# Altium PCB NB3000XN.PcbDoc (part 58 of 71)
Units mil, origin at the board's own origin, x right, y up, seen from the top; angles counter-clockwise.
Board outline 9527.56 x 6929.77 mil, 6 copper layers (Top Layer, GND+SHIELD, MidLayer1, MidLayer2, P2 - 3V3+5V0, Bottom Layer), stack 62.375 mil thick; 832 components, 1027 nets, 4655 pads, 4981 vias.
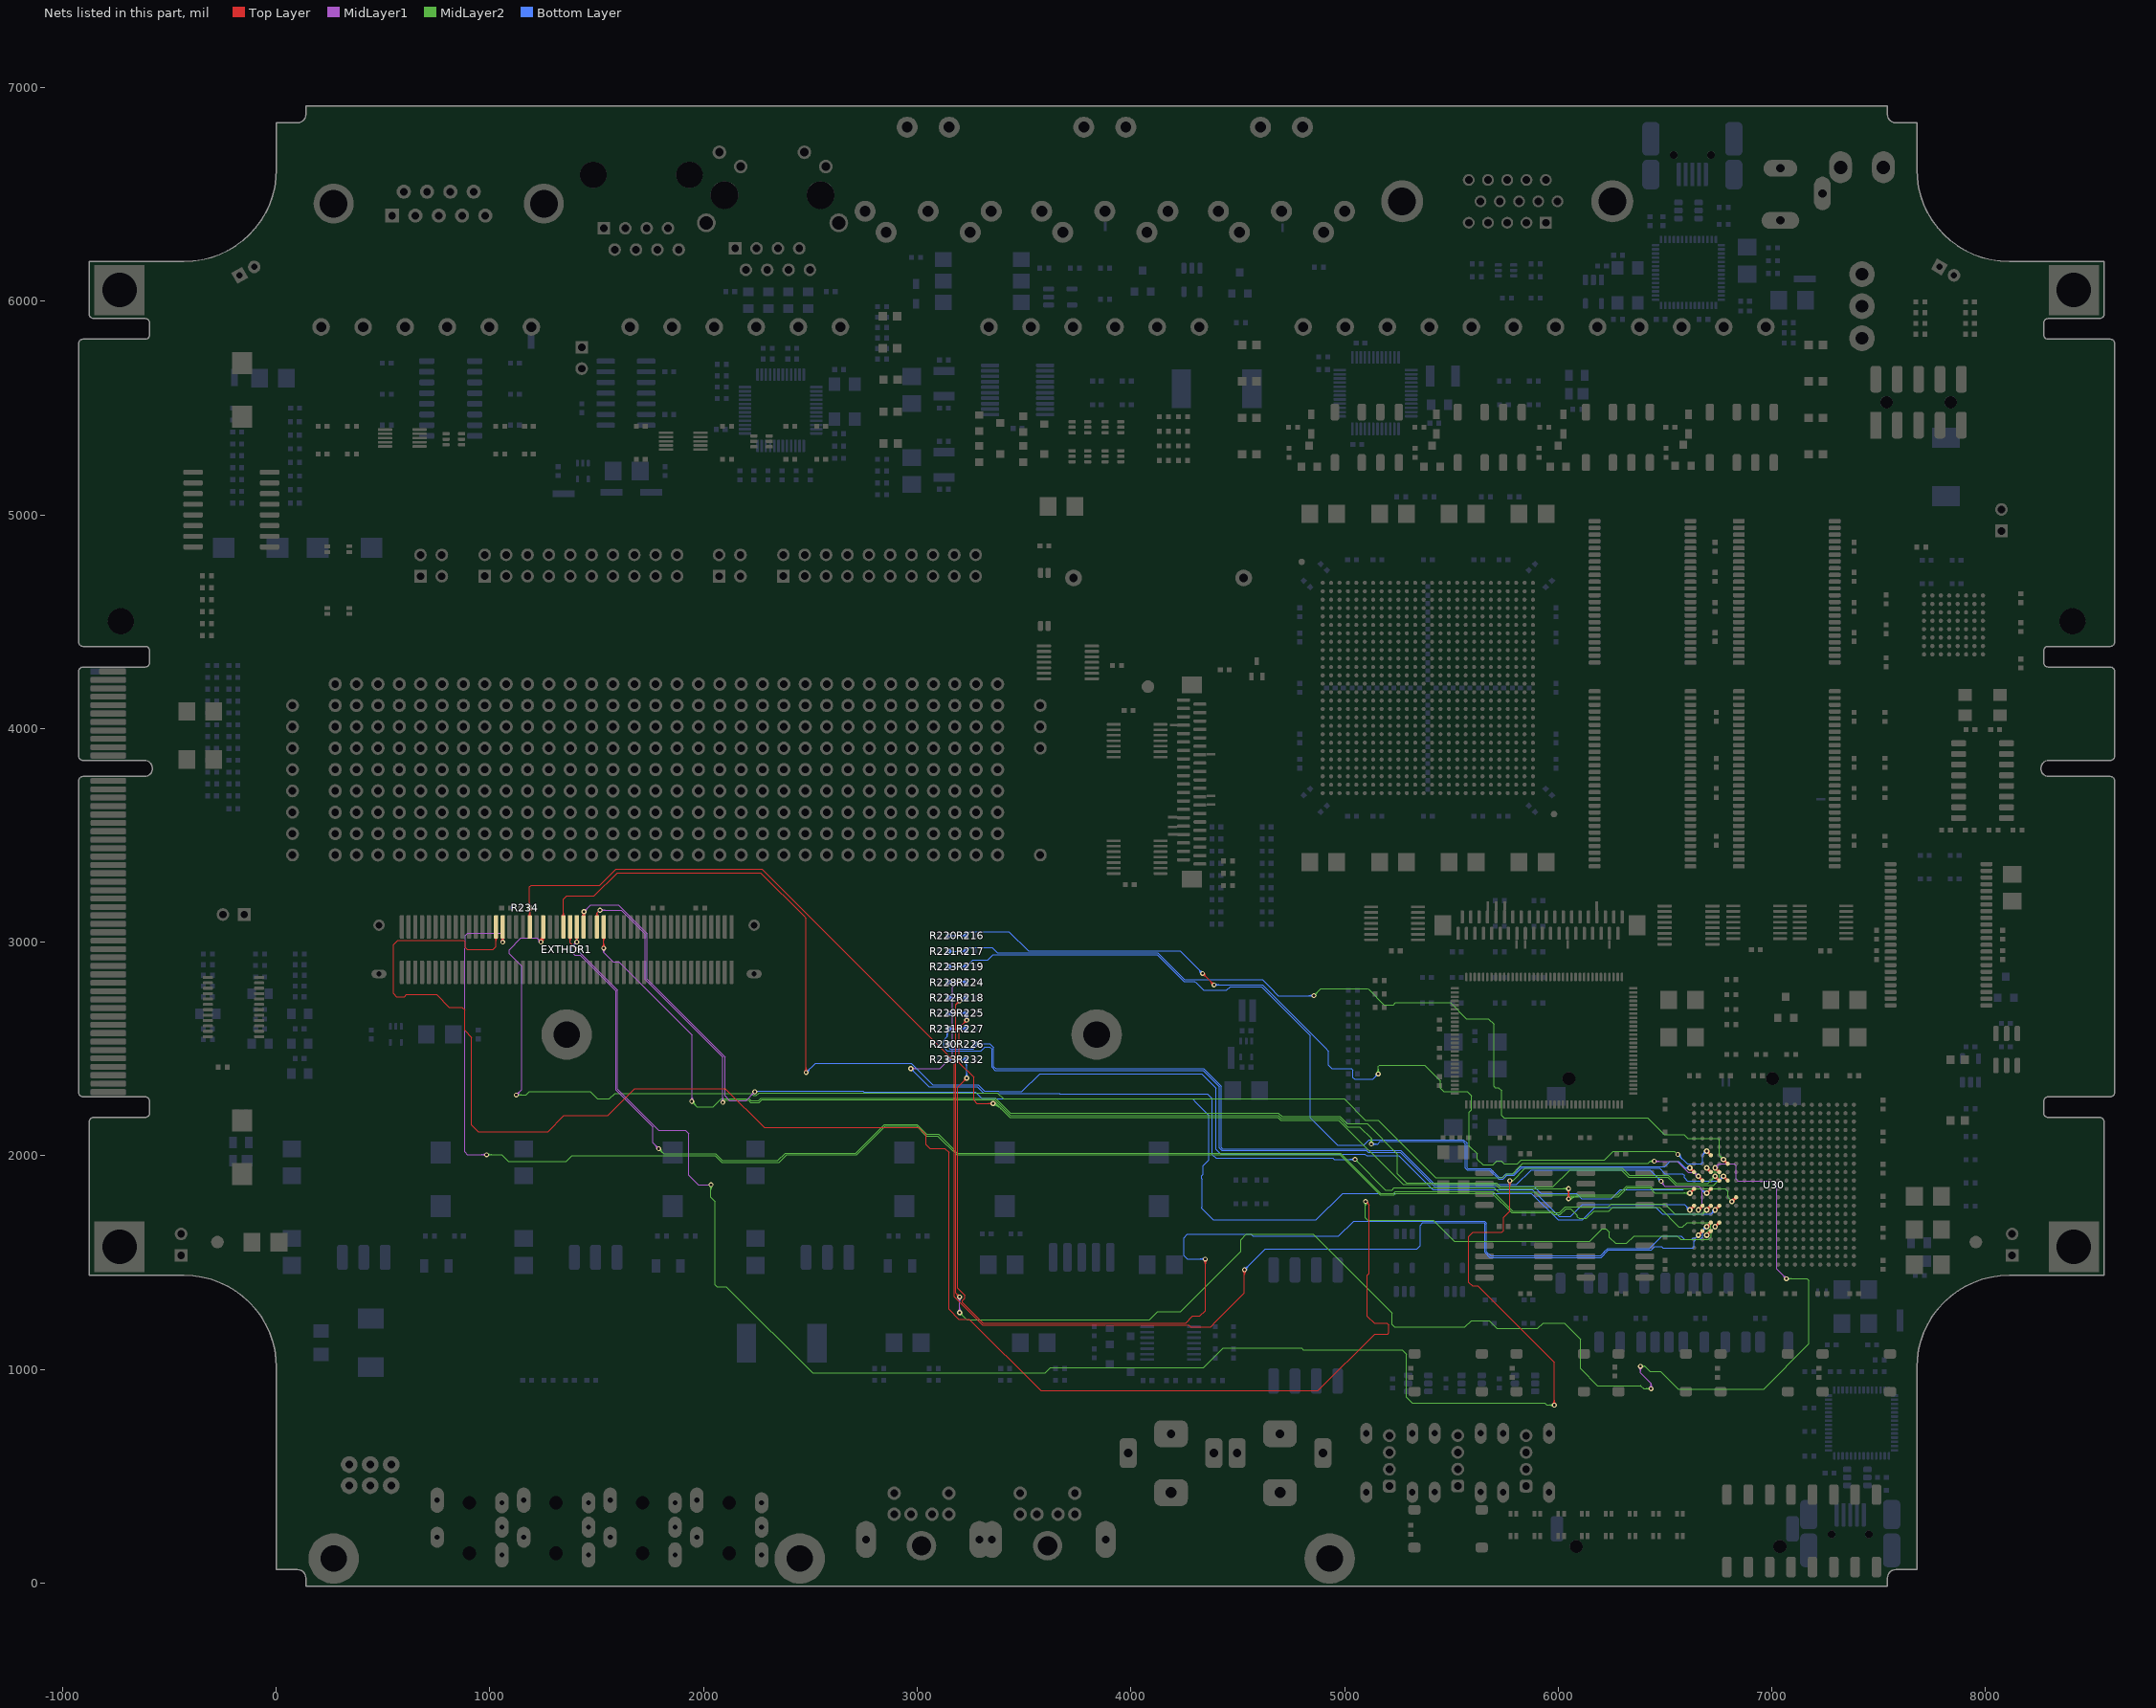
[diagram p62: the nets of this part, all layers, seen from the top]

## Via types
v1: diameter 23, hole 11.81, Top Layer to Bottom Layer, 3672 vias
v2: diameter 26, hole 11.81, Top Layer to Bottom Layer, 461 vias
v3: diameter 19, hole 11.81, Top Layer to Bottom Layer, tented both sides, 396 vias
v4: diameter 23.62, hole 11.81, Top Layer to Bottom Layer, 288 vias
v5: diameter 20, hole 11.81, Top Layer to Bottom Layer, 91 vias
v6: diameter 23, hole 11.81, Top Layer to Bottom Layer, tented both sides, 50 vias
v7: diameter 31, hole 11.81, Top Layer to Bottom Layer, 15 vias
v8: diameter 27.56, hole 11.81, Top Layer to Bottom Layer, tented both sides, 4 vias
v9: diameter 29, hole 11.81, Top Layer to Bottom Layer, 3 vias
v10: diameter 21, hole 11.81, Top Layer to Bottom Layer, 1 vias

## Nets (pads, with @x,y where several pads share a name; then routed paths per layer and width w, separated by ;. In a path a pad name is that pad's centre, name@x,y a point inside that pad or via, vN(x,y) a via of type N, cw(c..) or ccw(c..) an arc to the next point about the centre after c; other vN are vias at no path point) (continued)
PB_SPI.SCLK: EXTHDR1.57 U30.W10 | length 7349.8
  Top Layer w4: v1@1232.79,3007.44 ccw(c1192.61,3047.62) EXTHDR1.57@1249.43,3047.62 ; v1@1235.62,3004.61 ccw(c1202.27,3037.97) EXTHDR1.57@1249.43,3037.97 ; v1@1238.45,3001.79 ccw(c1211.92,3028.31) EXTHDR1.57@1249.43,3028.31 ; v1(1239.51,3000.72) 1240.19,3000.04 1249.43,3009.28 ; v1@1241.27,2998.96 ccw(c1221.58,3018.65) EXTHDR1.57@1249.43,3018.65 ; v1@1244.1,2996.13 ccw(c1231.24,3008.99) 1249.43,3008.99 ; EXTHDR1.57@1244.21,3020.67 cw(c1234.41,3009.28) 1249.43,3009.28 ; EXTHDR1.57@1249.43,3071.85 1249.43,3009.28 ; EXTHDR1.57@1254.65,3020.67 ccw(c1264.46,3009.28) 1249.43,3009.28
  Top Layer w8: v2@6655.67,1895.37 cw(c6655.67,1873.64) 6671.03,1889.01 cw(c6686.4,1904.37) v2@6664.67,1904.37 ; v2(6655.67,1904.37) U30.W10@6675.35,1884.68 ; U30.W10@6669.51,1884.68 ccw(c6655.41,1884.68) 6665.38,1894.66 ccw(c6675.35,1904.63) U30.W10@6675.35,1890.53
  MidLayer1 w4: v1(1123.52,2285.04) 1148.86,2310.37 1148.86,2888 1090,2946.86 1090,2965 1145,3020 1220.23,3020 v1(1239.51,3000.72) ; v1@1123.52,2290.54 ccw(c1123.52,2303.82) 1132.91,2294.43 ccw(c1142.3,2285.04) v1@1129.02,2285.04 ; v1@1123.52,2294.54 ccw(c1123.52,2317.48) 1139.74,2301.26 ccw(c1155.96,2285.04) v1@1133.02,2285.04 ; v1@1230.01,3000.72 ccw(c1207.07,3000.72) 1223.29,3016.94 ccw(c1239.51,3033.16) v1@1239.51,3010.22 ; v1@1234.01,3000.72 ccw(c1220.73,3000.72) 1230.12,3010.11 ccw(c1239.51,3019.5) v1@1239.51,3006.22 ; v1(6449.52,1975.04) 6556.86,1975.04 6608.19,1923.71 6636.33,1923.71 v2(6655.67,1904.37) ; v1@6453.41,1971.15 cw(c6462.8,1961.76) 6462.8,1975.04 cw(c6462.8,1988.32) v1@6453.41,1978.93 ; v1@6456.24,1968.32 cw(c6472.46,1952.11) 6472.46,1975.04 cw(c6472.46,1997.98) v1@6456.24,1981.76 ; v2@6644.67,1904.37 ccw(c6618.11,1904.37) 6636.89,1923.15 ccw(c6655.67,1941.93) v2@6655.67,1915.37 ; v2@6648.67,1904.37 ccw(c6631.77,1904.37) 6643.72,1916.32 ccw(c6655.67,1928.27) v2@6655.67,1911.37
  MidLayer2 w4: v1(1123.52,2285.04) 1170.04,2285.04 1185.37,2300.37 1469.63,2300.37 1503.29,2266.71 1560,2266.71 1585.29,2292 2223.25,2292 2232.75,2282.5 2247.25,2282.5 2259.25,2294.5 3375.5,2294.5 3403.3,2266.71 4998.52,2266.71 5098.52,2166.71 5156.86,2166.71 5425.7,1897.87 5740.64,1897.87 5759.65,1916.87 5786.05,1916.87 5815.71,1946.54 5834.88,1965.71 6420.71,1965.71 6430.04,1975.04 ; v1@1127.41,2281.15 cw(c1136.8,2271.76) 1136.8,2285.04 cw(c1136.8,2298.32) v1@1127.41,2288.93 ; v1@1130.24,2278.32 cw(c1146.46,2262.11) 1146.46,2285.04 cw(c1146.46,2307.98) v1@1130.24,2291.76 ; v1@6442.04,1969.19 ccw(c6430.04,1959.81) 6430.04,1975.04 ; v1@6442.04,1980.89 cw(c6430.04,1990.27) 6430.04,1975.04 ; v1(6449.52,1975.04) 6430.04,1975.04
PBCTRL.1W.ID: EXTHDR1.61 R234.1 U30.V15 | length 8232
  Top Layer w4: R234.1@1179.59,3152.92 cw(c1163.06,3136.38) 1186.44,3136.38 ; R234.1@1179.59,3167.08 ccw(c1163.68,3182.99) 1186.18,3182.99 ccw(c1208.68,3182.99) R234.1@1192.77,3167.08 ; EXTHDR1.61@1180.78,3122.62 ccw(c1167.12,3136.28) 1186.44,3136.28 ccw(c1205.75,3136.28) EXTHDR1.61@1192.1,3122.62 ; R234.1@1182.42,3155.75 cw(c1172.71,3146.04) 1186.44,3146.04 ; R234.1@1182.42,3164.25 ccw(c1173.34,3173.33) 1186.18,3173.33 ccw(c1199.02,3173.33) R234.1@1189.94,3164.25 ; EXTHDR1.61@1186.44,3071.85 1186.44,3159.74 R234.1@1186.18,3160 1186.18,3258.71 1194.18,3266.71 1515.19,3266.71 1590.19,3341.71 2273.52,3341.71 3112.7,2502.53 3173.19,2442.04 3173.19,1340.35 3305.17,1208.37 4271.63,1208.37 4280,1200 4373.48,1200 4400.9,1227.42 4531.86,1358.37 v1(4531.86,1466.71) ; 1186.44,3137.64 cw(c1208.05,3137.64) R234.1@1192.77,3152.92 ; 1186.44,3147.29 cw(c1198.4,3147.29) R234.1@1189.94,3155.75 ; v1@4525.14,1459.99 cw(c4508.92,1443.77) 4531.86,1443.77 cw(c4554.79,1443.77) v1@4538.57,1459.99 ; v1@4527.97,1462.82 cw(c4518.58,1453.43) 4531.86,1453.43 cw(c4545.14,1453.43) v1@4535.75,1462.82
  Top Layer w8: v2(6695.04,1668.15) U30.V15@6714.72,1687.83 ; v2@6695.04,1677.15 ccw(c6695.04,1698.88) 6710.4,1683.51 ccw(c6725.77,1668.15) v2@6704.04,1668.15 ; U30.V15@6708.88,1687.83 cw(c6694.78,1687.83) 6704.75,1677.86 cw(c6714.72,1667.89) U30.V15@6714.72,1681.99
  Bottom Layer w4: v1(4531.86,1466.71) 4630.15,1565 5340,1565 5355,1580 5355,1675 5367,1687 5651.69,1687 5657,1681.69 5657,1548.04 5680,1525.04 6202.19,1525.04 6235.86,1558.71 6436.52,1558.71 6452.86,1575.04 6484.52,1575.04 6490.19,1569.37 6631.52,1569.37 6635.52,1573.37 6635.52,1600.04 6644.19,1608.71 6662.86,1608.71 6675.52,1621.37 6675.52,1648.63 v2(6695.04,1668.15) ; v1@4531.86,1472.21 ccw(c4531.86,1485.49) 4541.25,1476.1 ccw(c4550.64,1466.71) v1@4537.36,1466.71 ; v1@4531.86,1476.21 ccw(c4531.86,1499.14) 4548.07,1482.93 ccw(c4564.29,1466.71) v1@4541.36,1466.71 ; 6683.09,1656.2 ccw(c6671.14,1668.15) v2@6688.04,1668.15 ; 6683.09,1656.2 cw(c6695.04,1644.25) v2@6695.04,1661.15 ; v2@6684.04,1668.15 cw(c6657.48,1668.15) 6676.26,1649.37 cw(c6695.04,1630.6) v2@6695.04,1657.15
PBCTRL.1W.PIO1: EXTHDR1.69 U30.V16 | length 7898.4
  Top Layer w4: v1@1053.74,3007.17 ccw(c1037.52,3023.39) 1060.46,3023.39 ccw(c1083.39,3023.39) v1@1067.17,3007.17 ; v1@1056.57,3004.34 ccw(c1047.18,3013.73) 1060.46,3013.73 ccw(c1073.73,3013.73) v1@1064.34,3004.34 ; v1(1060.46,3000.46) EXTHDR1.69@1060.46,3071.85
  Top Layer w8: v2(6695.04,1628.78) U30.V16@6714.72,1648.46 ; v2@6695.04,1637.78 ccw(c6695.04,1659.51) 6710.4,1644.14 ccw(c6725.77,1628.78) v2@6704.04,1628.78 ; U30.V16@6708.88,1648.46 cw(c6694.78,1648.46) 6704.75,1638.49 cw(c6714.72,1628.52) U30.V16@6714.72,1642.62
  MidLayer1 w4: v1@978.28,1998.28 ccw(c962.06,1982.06) 962.06,2005 ccw(c962.06,2027.93) v1@978.28,2011.72 ; v1@981.11,2001.11 ccw(c971.72,1991.72) 971.72,2005 ccw(c971.72,2018.28) v1@981.11,2008.89 ; v1(985,2005) 895,2005 881.86,2018.14 881.86,2970.71 886.19,2975.04 886.19,3031.19 896.71,3041.71 1053.29,3041.71 1060.46,3034.54 v1(1060.46,3000.46) ; v1@1053.74,3007.17 ccw(c1037.52,3023.39) 1060.46,3023.39 ccw(c1083.39,3023.39) v1@1067.17,3007.17 ; v1@1056.57,3004.34 ccw(c1047.18,3013.73) 1060.46,3013.73 ccw(c1073.73,3013.73) v1@1064.34,3004.34
  MidLayer2 w4: v1(985,2005) 1055,2005 1086.69,1973.31 1358.27,1973.31 1385,2000.04 2055,2000.04 2065.04,1990 2085.04,1970 2354.96,1970 2389.77,2004.81 2716.63,2004.81 2850.82,2139 2995.87,2139 3041.37,2093.5 3095.73,2093.5 3184.42,2004.81 4978.09,2004.81 5166.19,1816.71 5232.47,1816.71 5240.8,1825.04 5690.19,1825.04 5781.86,1733.37 5970.54,1733.37 5978.92,1725 5995,1725 6009.52,1725.04 6037.19,1752.71 6057.86,1752.71 6090.19,1720.37 6090.19,1715.04 6098.52,1706.71 6131.86,1706.71 6166.86,1741.71 6237.82,1741.71 6254.49,1758.37 6473.52,1758.37 6565.19,1666.71 6581.86,1666.71 6603.52,1688.37 6680,1688.37 6681.23,1687.15 6702.91,1687.15 6714.04,1676.02 6714.04,1660.28 6695.04,1641.28 v2(6695.04,1628.78) ; v1@988.89,2001.11 cw(c998.28,1991.72) 998.28,2005 cw(c998.28,2018.28) v1@988.89,2008.89 ; v1@991.72,1998.28 cw(c1007.93,1982.06) 1007.93,2005 cw(c1007.93,2027.93) v1@991.72,2011.72
PBCTRL.1W.PIO2: EXTHDR1.71 U30.U15 | length 10109.7
  Top Layer w4: EXTHDR1.71@1023.3,3021.07 cw(c1009.65,3007.42) 1028.96,3007.42 cw(c1048.27,3007.42) EXTHDR1.71@1034.62,3021.07 ; EXTHDR1.71@1031.86,3075.04 1028.96,3075.04 EXTHDR1.71@1028.96,3071.85 1028.96,2980.48 1015.19,2966.71 894.52,2966.71 886.19,2975.04 886.19,3000.04 877.86,3008.37 568.37,3008.37 548.52,2988.52 548.52,2760 563.52,2745 600,2745 610,2755 750,2755 810,2695 870,2695 881.86,2683.14 881.86,2588.14 915,2555 915,2143.9 944.9,2114 1271.63,2114 1346.63,2189 1552.94,2189 1678.94,2315 2101.06,2315 2284.06,2132 3006.69,2132 3042,2096.69 3042,2053 3060,2035 3130,2035 3148.86,2016.14 3148.86,1281.14 3195,1235 3243.92,1235 3578.54,900.37 4875.37,900.37 5141.71,1166.71 5201.71,1166.71 5206.69,1171.69 5206.69,1208.31 5198.29,1216.71 5139.19,1216.71 5106.86,1249.04 5106.86,1441.71 5115.19,1450.04 5115.19,1770.04 v1(5098.52,1786.71) ; v1@5098.52,1777.21 cw(c5098.52,1754.27) 5114.74,1770.49 cw(c5130.96,1786.71) v1@5108.02,1786.71 ; v1@5098.52,1781.21 cw(c5098.52,1767.93) 5107.91,1777.32 cw(c5117.3,1786.71) v1@5104.02,1786.71
  Top Layer w8: v2(6734.41,1668.15) U30.U15@6754.09,1687.83 ; v2@6734.41,1677.15 ccw(c6734.41,1698.88) 6749.77,1683.51 ccw(c6765.14,1668.15) v2@6743.41,1668.15 ; U30.U15@6748.25,1687.83 cw(c6734.15,1687.83) 6744.12,1677.86 cw(c6754.09,1667.89) U30.U15@6754.09,1681.99
  MidLayer2 w4: v1@5092.62,1779.27 cw(c5082.92,1767.04) 5098.52,1767.04 cw(c5114.13,1767.04) v1@5104.43,1779.27 ; v1(5098.52,1786.71) 5098.52,1709.48 5109.29,1698.71 5414.76,1698.71 5513.43,1600.04 6147.52,1600.04 6205.86,1658.37 6223.52,1658.37 6240.19,1641.71 6240.19,1619.04 6268.52,1590.71 6320.67,1590.71 6355,1625.04 6558.19,1625.04 6573.52,1609.71 6655,1609.71 6655.07,1609.78 6702.91,1609.78 6715.41,1622.28 6715.41,1649.15 v2@6732.97,1666.71 ; v2@6731.86,1666.71 v2@6732.97,1666.71 ; v2@6732.97,1666.71 6734.4,1666.71 v2(6734.41,1668.15) v2@6732.97,1666.71
PBCTRL.CLK.CLK0: EXTHDR1.51 U30.Y13 | length 7160.4
  Top Layer w4: EXTHDR1.51@1338.26,3122.62 ccw(c1324.61,3136.28) 1343.92,3136.28 ccw(c1363.23,3136.28) EXTHDR1.51@1349.58,3122.62 ; EXTHDR1.51@1343.92,3071.85 1343.92,3200.79 1360.17,3217.04 1488.15,3217.04 1596.15,3325.04 2267.56,3325.04 2467.3,3125.3 2480,3112.6 v1(2480,2390) ; v1@2473.28,2396.72 ccw(c2457.06,2412.93) 2480,2412.93 ccw(c2502.93,2412.93) v1@2486.72,2396.72 ; v1@2476.11,2393.89 ccw(c2466.72,2403.28) 2480,2403.28 ccw(c2493.28,2403.28) v1@2483.89,2393.89
  Top Layer w8: v2(6616.3,1746.89) U30.Y13@6635.98,1766.57 ; v2@6616.3,1755.89 ccw(c6616.3,1777.62) 6631.66,1762.25 ccw(c6647.03,1746.89) v2@6625.3,1746.89 ; U30.Y13@6630.14,1766.57 cw(c6616.04,1766.57) 6626.01,1756.6 cw(c6635.98,1746.63) U30.Y13@6635.98,1760.73
  Bottom Layer w4: v1(2480,2390) 2523.37,2433.37 2971.67,2433.37 3073.54,2331.5 3285.34,2331.5 3314.34,2302.5 3378.82,2302.5 3381.28,2300.04 3490.19,2300.04 3573.52,2383.37 4331.86,2383.37 4398.52,2316.71 4398.52,2050 ; v1@2480,2395.5 ccw(c2480,2408.78) 2489.39,2399.39 ccw(c2498.78,2390) v1@2485.5,2390 ; v1@2480,2399.5 ccw(c2480,2422.43) 2496.22,2406.22 ccw(c2512.43,2390) v1@2489.5,2390 ; 4398.52,2035 4398.52,2050 ; v2@6605.3,1746.89 ccw(c6578.74,1746.89) 6597.52,1765.67 ccw(c6616.3,1784.45) v2@6616.3,1757.89 ; v2@6609.3,1746.89 ccw(c6592.4,1746.89) 6604.35,1758.84 ccw(c6616.3,1770.79) v2@6616.3,1753.89 ; v2(6616.3,1746.89) 6590.76,1772.43 6114.24,1772.43 6058.52,1716.71 6004.86,1716.71 5879.86,1841.71 5412.21,1841.71 5253.21,2000.71 5103.94,2000.71 5096.27,2008.37 4420,2008.37 4398.52,2029.85 4398.52,2050
PBCTRL.CLK.CLK1: EXTHDR1.45 U30.U13 | length 7057.2
  Top Layer w4: EXTHDR1.45@1432.75,3122.62 ccw(c1419.09,3136.28) 1438.41,3136.28 ccw(c1457.72,3136.28) EXTHDR1.45@1444.07,3122.62 ; v1@1433.47,3136.32 cw(c1421.55,3124.41) EXTHDR1.45@1438.41,3124.41 ; EXTHDR1.45@1438.41,3071.85 v1@1438.41,3141.26 ; EXTHDR1.45@1438.41,3115.81 cw(c1467.42,3115.81) v1@1446.91,3136.32 ; EXTHDR1.45@1438.41,3125.46 cw(c1457.77,3125.46) v1@1444.08,3139.15
  Top Layer w8: v2(6734.41,1746.89) U30.U13@6754.09,1766.57 ; v2@6734.41,1755.89 ccw(c6734.41,1777.62) 6749.77,1762.25 ccw(c6765.14,1746.89) v2@6743.41,1746.89 ; U30.U13@6748.25,1766.57 cw(c6734.15,1766.57) 6744.12,1756.6 cw(c6754.09,1746.63) U30.U13@6754.09,1760.73
  MidLayer1 w4: v1(1440.19,3143.04) 1472.19,3175.04 1600.9,3175.04 1735,3040.94 1735,2827.86 1771.25,2791.61 2100,2462.86 2100,2280 2120.63,2259.37 2199.37,2259.37 v1(2240,2300) ; v1@1440.19,3148.54 ccw(c1440.19,3161.82) 1449.58,3152.43 ccw(c1458.97,3143.04) v1@1445.69,3143.04 ; v1@1440.19,3152.54 ccw(c1440.19,3175.48) 1456.41,3159.26 ccw(c1472.63,3143.04) v1@1449.69,3143.04 ; v1@2230.5,2300 cw(c2207.56,2300) 2223.78,2283.78 cw(c2240,2267.56) v1@2240,2290.5 ; v1@2234.5,2300 cw(c2221.22,2300) 2230.61,2290.61 cw(c2240,2281.22) v1@2240,2294.5
  Bottom Layer w4: v1(2240,2300) 2243,2303 2745.94,2303 2749.44,2299.5 3272.08,2299.5 3301.08,2270.5 3365.56,2270.5 3369.19,2266.87 4288.31,2266.87 4305.35,2249.84 4365.52,2189.66 4365.52,1980.81 4338,1953.29 4338,1914.27 4331.02,1907.29 4331.02,1892.79 4333,1890.82 4333,1761.69 4331.02,1759.71 4331.02,1754.23 4385.21,1700.04 4650,1700.04 4867.56,1700.04 4992.56,1825.04 5873.9,1825.04 5998.9,1700.04 6115.19,1700.04 6173.36,1758.21 6457.02,1758.21 6487.34,1727.89 6715.41,1727.89 v2(6734.41,1746.89) ; v2@6723.41,1746.89 cw(c6696.85,1746.89) 6715.63,1728.11 cw(c6734.41,1709.33) v2@6734.41,1735.89 ; v2@6727.41,1746.89 cw(c6710.51,1746.89) 6722.46,1734.94 cw(c6734.41,1722.99) v2@6734.41,1739.89
PBCTRL.CLK.CLK2: EXTHDR1.47 U30.V13 | length 6820.2
  Top Layer w4: EXTHDR1.47@1401.26,3021.07 cw(c1387.73,3007.55) v1@1406.86,3007.55 ; EXTHDR1.47@1405.05,3018.95 cw(c1404.49,3016.65) 1406.86,3016.65 ; EXTHDR1.47@1405.14,3018.93 cw(c1404.63,3016.71) 1406.91,3016.71 ; v1(1406.86,3001.04) 1406.86,3016.65 ; v1@1406.86,3007.28 cw(c1426.36,3007.28) EXTHDR1.47@1412.57,3021.07 ; EXTHDR1.47@1406.91,3071.85 1406.91,3016.71 ; 1406.86,3016.65 cw(c1409.19,3016.65) 1408.68,3018.93 ccw(c1409.19,3016.71) 1406.91,3016.71 ; 1406.86,3016.65 1406.91,3016.71
  Top Layer w8: v2(6695.04,1746.89) U30.V13@6714.72,1766.57 ; v2@6695.04,1755.89 ccw(c6695.04,1777.62) 6710.4,1762.25 ccw(c6725.77,1746.89) v2@6704.04,1746.89 ; U30.V13@6708.88,1766.57 cw(c6694.78,1766.57) 6704.75,1756.6 cw(c6714.72,1746.63) U30.V13@6714.72,1760.73
  MidLayer1 w4: v1@1397.36,3001.04 cw(c1374.42,3001.04) 1390.64,2984.82 cw(c1406.86,2968.61) v1@1406.86,2991.54 ; v1@1401.36,3001.04 cw(c1388.08,3001.04) 1397.47,2991.65 cw(c1406.86,2982.26) v1@1406.86,2995.54 ; v1(1406.86,3001.04) 1381.86,2976.04 1381.86,2955 1396.86,2940 1422.25,2940 1590.19,2772.06 1590.19,2308.5 1762.7,2135.99 1762.7,2060.87 v1(1790.19,2033.37) ; v1@1780.69,2033.37 ccw(c1757.76,2033.37) 1773.97,2049.59 ccw(c1790.19,2065.81) v1@1790.19,2042.87 ; v1@1784.69,2033.37 ccw(c1771.41,2033.37) 1780.8,2042.76 ccw(c1790.19,2052.15) v1@1790.19,2038.87
  MidLayer2 w4: v1@1790.19,2023.87 cw(c1790.19,2000.94) 1806.41,2017.16 cw(c1822.63,2033.37) v1@1799.69,2033.37 ; v1@1790.19,2027.87 cw(c1790.19,2014.6) 1799.58,2023.99 cw(c1808.97,2033.37) v1@1795.69,2033.37 ; v1(1790.19,2033.37) 1813.56,2010 2056.35,2010 2088.35,1978 2348,1978 2382.81,2012.81 2713.31,2012.81 2847.5,2147 2999.19,2147 3044.69,2101.5 3099.05,2101.5 3150.51,2050.04 3187.74,2012.81 4981.42,2012.81 5169.52,1824.71 5229.15,1824.71 5238.31,1833.87 5694.03,1833.87 5694.52,1833.37 5786.19,1741.71 5973.52,1741.71 5981.86,1733.37 6005.52,1733.37 6032.86,1760.71 6234.19,1760.71 6248.52,1775.04 6498.52,1775.04 6545.86,1727.71 6675.86,1727.71 v2(6695.04,1746.89) ; v2@6684.04,1746.89 cw(c6657.48,1746.89) 6676.26,1728.11 cw(c6695.04,1709.33) v2@6695.04,1735.89 ; v2@6688.04,1746.89 cw(c6671.14,1746.89) 6683.09,1734.94 cw(c6695.04,1722.99) v2@6695.04,1739.89
PBCTRL.CLK.EN: EXTHDR1.49 U30.U10 | length 9381.3
  Top Layer w4: EXTHDR1.49@1369.76,3021.07 cw(c1356.1,3007.42) 1375.42,3007.42 cw(c1394.73,3007.42) EXTHDR1.49@1381.07,3021.07 ; EXTHDR1.49@1375.42,3071.85 1375.42,2998.15 v1(1406.86,2966.71) ; v1@1397.36,2966.71 ccw(c1374.42,2966.71) 1390.64,2982.93 ccw(c1406.86,2999.14) v1@1406.86,2976.21 ; v1@1401.36,2966.71 ccw(c1388.08,2966.71) 1397.47,2976.1 ccw(c1406.86,2985.49) v1@1406.86,2972.21 ; v1@5766.81,1876.66 cw(c5750.59,1860.44) 5773.52,1860.44 cw(c5796.46,1860.44) v1@5780.24,1876.66 ; v1@5769.64,1879.49 cw(c5760.25,1870.1) 5773.52,1870.1 cw(c5786.8,1870.1) v1@5777.41,1879.49 ; v1(5773.52,1883.37) 5773.52,1741.71 5744.19,1712.37 5744.19,1650.04 5735.86,1641.71 5601.71,1641.71 5581.86,1621.86 5581.86,1408.37 5598.52,1391.71 5623.52,1391.71 5981.86,1033.37 v1(5981.86,833.37) ; v1@5975.14,840.09 ccw(c5958.92,856.31) 5981.86,856.31 ccw(c6004.79,856.31) v1@5988.57,840.09 ; v1@5977.97,837.26 ccw(c5968.58,846.65) 5981.86,846.65 ccw(c5995.14,846.65) v1@5985.75,837.26
  Top Layer w8: v2@6734.41,1895.37 cw(c6734.41,1873.64) 6749.77,1889.01 cw(c6765.14,1904.37) v2@6743.41,1904.37 ; v2(6734.41,1904.37) U30.U10@6754.09,1884.68 ; U30.U10@6748.25,1884.68 ccw(c6734.15,1884.68) 6744.12,1894.66 ccw(c6754.09,1904.63) U30.U10@6754.09,1890.53
  MidLayer1 w4: v1@1406.86,2957.21 cw(c1406.86,2934.27) 1423.07,2950.49 cw(c1439.29,2966.71) v1@1416.36,2966.71 ; v1@1406.86,2961.21 cw(c1406.86,2947.93) 1416.25,2957.32 cw(c1425.64,2966.71) v1@1412.36,2966.71 ; v1(1406.86,2966.71) 1598.19,2775.37 1598.19,2311.81 1790,2120 1915,2120 1930,2105 1930,1910.23 1975.23,1865 v1(2035,1865)
  MidLayer2 w4: v1@2028.28,1858.28 cw(c2012.06,1842.06) 2035,1842.06 cw(c2057.93,1842.06) v1@2041.72,1858.28 ; v1@2031.11,1861.11 cw(c2021.72,1851.72) 2035,1851.72 cw(c2048.28,1851.72) v1@2038.89,1861.11 ; v1(2035,1865) 2035,1805.23 2055,1785.23 2055,1397 2064,1388 2105.82,1388 2125.99,1367.83 2510.45,983.37 3598.52,983.37 3623.19,1008.04 4340,1008.04 4431.96,1100 4550,1100 4798.52,1100.04 4807.19,1091.37 5270.88,1091.37 5290.19,1072.06 5290.19,869.81 5317.13,842.87 5937.13,842.87 5946.63,833.37 v1(5981.86,833.37) ; v1(5773.52,1883.37) 5786.49,1883.37 5844.82,1941.71 6299.23,1941.71 6332.56,1908.37 6515.19,1908.37 6553.52,1870.04 6700.08,1870.04 v2(6734.41,1904.37) ; v1@5975.14,826.66 ccw(c5958.92,810.44) 5958.92,833.37 ccw(c5958.92,856.31) v1@5975.14,840.09 ; v1@5977.97,829.49 ccw(c5968.58,820.1) 5968.58,833.37 ccw(c5968.58,846.65) v1@5977.97,837.26 ; v2@6723.41,1904.37 cw(c6696.85,1904.37) 6715.63,1885.59 cw(c6734.41,1866.81) v2@6734.41,1893.37 ; v2@6727.41,1904.37 cw(c6710.51,1904.37) 6722.46,1892.42 cw(c6734.41,1880.47) v2@6734.41,1897.37
PBCTRL.JTAG.DETECT: R232.1 R233.1 U30.W16 | length 6012.9
  Top Layer w4: v1@3222.36,2363.71 cw(c3199.42,2363.71) 3215.64,2347.49 cw(c3231.86,2331.27) v1@3231.86,2354.21 ; v1@3226.36,2363.71 cw(c3213.08,2363.71) 3222.47,2354.32 cw(c3231.86,2344.93) v1@3231.86,2358.21 ; v1(3231.86,2363.71) 3189.19,2321.04 3189.19,1380.81 3222.5,1347.5 3222.5,1332.75 3212.25,1322.5 3212.25,1312.61 3308.15,1216.71 4256.67,1216.71 4290,1250.04 4323.52,1250.04 4348.52,1275.04 v1(4348.52,1516.71) ; v1@4341.81,1509.99 cw(c4325.59,1493.77) 4348.52,1493.77 cw(c4371.46,1493.77) v1@4355.24,1509.99 ; v1@4344.64,1512.82 cw(c4335.25,1503.43) 4348.52,1503.43 cw(c4361.8,1503.43) v1@4352.41,1512.82
  Top Layer w8: v2(6655.67,1628.78) U30.W16@6675.35,1648.46 ; v2@6655.67,1637.78 ccw(c6655.67,1659.51) 6671.03,1644.14 ccw(c6686.4,1628.78) v2@6664.67,1628.78 ; U30.W16@6669.51,1648.46 cw(c6655.41,1648.46) 6665.38,1638.49 cw(c6675.35,1628.52) U30.W16@6675.35,1642.62
  Bottom Layer w4: R233.1@3146.18,2450 R232.1@3228.82,2450 3228.82,2425.08 3231.86,2422.04 v1(3231.86,2363.71) ; R233.1@3149.94,2446.24 cw(c3159.02,2437.16) 3159.02,2450 cw(c3159.02,2462.84) R233.1@3149.94,2453.76 ; R233.1@3152.77,2443.41 cw(c3168.68,2427.5) 3168.68,2450 cw(c3168.68,2472.5) R233.1@3152.77,2456.59 ; R232.1@3222.23,2442.92 cw(c3206.32,2427.01) 3228.82,2427.01 cw(c3251.32,2427.01) R232.1@3235.41,2442.92 ; R232.1@3222.23,2443.41 ccw(c3206.32,2427.5) 3206.32,2450 ccw(c3206.32,2472.5) R232.1@3222.23,2456.59 ; R232.1@3225.06,2445.75 cw(c3215.98,2436.67) 3228.82,2436.67 cw(c3241.66,2436.67) R232.1@3232.58,2445.75 ; R232.1@3225.06,2446.24 ccw(c3215.98,2437.16) 3215.98,2450 ccw(c3215.98,2462.84) R232.1@3225.06,2453.76 ; v1@3225.14,2370.43 ccw(c3208.92,2386.64) 3231.86,2386.64 ccw(c3254.79,2386.64) v1@3238.57,2370.43 ; v1@3227.97,2367.6 ccw(c3218.58,2376.99) 3231.86,2376.99 ccw(c3245.14,2376.99) v1@3235.75,2367.6 ; v1@4341.81,1509.99 ccw(c4325.59,1493.77) 4325.59,1516.71 ccw(c4325.59,1539.64) v1@4341.81,1523.43 ; v1@4344.64,1512.82 ccw(c4335.25,1503.43) 4335.25,1516.71 ccw(c4335.25,1529.99) v1@4344.64,1520.6 ; v1(4348.52,1516.71) 4265.19,1516.71 4248.52,1533.37 4248.52,1616.71 4265.19,1633.37 4562.21,1633.37 4570.58,1625 ; 4570.58,1624.71 4973,1624.71 5043.29,1695 5655,1695 5665,1685 5665,1551.35 5683.31,1533.04 6198.19,1533.04 6216.07,1550.92 ; 6215.19,1550.04 6231.86,1566.71 6428.19,1566.71 6486.52,1625.04 6574.86,1625.04 6590.19,1609.71 6624.19,1609.71 6631.19,1616.71 6643.6,1616.71 v2(6655.67,1628.78)
PBCTRL.JTAG.HARD.TCK: R219.1 R223.1 U30.Y9 | length 4593.8
  Top Layer w8: v2@6616.3,1934.74 cw(c6616.3,1913.01) 6631.66,1928.38 cw(c6647.03,1943.74) v2@6625.3,1943.74 ; v2(6616.3,1943.74) U30.Y9@6635.98,1924.06 ; U30.Y9@6630.14,1924.06 ccw(c6616.04,1924.06) 6626.01,1934.03 ccw(c6635.98,1944) U30.Y9@6635.98,1929.9
  Bottom Layer w4: R223.1@3146.18,2885 R219.1@3228.82,2885 3260.53,2916.71 3330,2916.71 3355.67,2942.37 4122.86,2942.37 4235.58,2829.66 4248.19,2817.04 4298.19,2817.04 4306.86,2808.37 4340.19,2775.04 4448.52,2775.04 4465.19,2791.71 4612.21,2791.71 4840.19,2563.73 4840.19,2177.02 4967.5,2049.71 5089.71,2049.71 5115,2075 5556.86,2075.04 5573.52,2058.37 5573.52,1945.37 5577.52,1941.37 5681.52,1941.37 5722.86,1900.04 5739.52,1900.04 5756.19,1916.71 5790.5,1916.71 5823.84,1950.04 6498.52,1950.04 6523.52,1975.04 6564,1975.04 6595.3,1943.74 ; R223.1@3149.94,2881.24 cw(c3159.02,2872.16) 3159.02,2885 cw(c3159.02,2897.84) R223.1@3149.94,2888.76 ; R223.1@3152.77,2878.41 cw(c3168.68,2862.5) 3168.68,2885 cw(c3168.68,2907.5) R223.1@3152.77,2891.59 ; R219.1@3222.23,2878.41 ccw(c3206.32,2862.5) 3206.32,2885 ccw(c3206.32,2907.5) R219.1@3222.23,2891.59 ; R219.1@3225.06,2881.24 ccw(c3215.98,2872.16) 3215.98,2885 ccw(c3215.98,2897.84) R219.1@3225.06,2888.76 ; R219.1@3228.82,2890.81 ccw(c3228.82,2904.84) R219.1@3238.74,2894.92 ; R219.1@3228.82,2894.81 ccw(c3228.82,2918.5) 3245.57,2901.75 ; R219.1@3234.14,2885.49 cw(c3245.79,2885.49) R219.1@3237.55,2893.73 ; R219.1@3238.14,2885.49 cw(c3259.45,2885.49) 3244.38,2900.56 ; v2@6607.26,1937.48 ccw(c6595.3,1929.2) 6595.3,1943.74 ; v2@6607.26,1950 cw(c6595.3,1958.28) 6595.3,1943.74 ; v2@6610.54,1939.75 ccw(c6602.94,1934.48) 6602.94,1943.74 ccw(c6602.94,1953) v2@6610.54,1947.73 ; v2(6616.3,1943.74) 6595.3,1943.74
PBCTRL.JTAG.HARD.TDI: R216.1 R220.1 U30.V7 | length 5126.8
  Top Layer w4: v1@4335.52,2844.21 cw(c4335.52,2821.27) 4351.74,2837.49 cw(c4367.96,2853.71) v1@4345.02,2853.71 ; v1@4335.52,2848.21 cw(c4335.52,2834.93) 4344.91,2844.32 cw(c4354.3,2853.71) v1@4341.02,2853.71 ; v1(4335.52,2853.71) v1(4389.19,2800.04) ; v1@4379.69,2800.04 ccw(c4356.76,2800.04) 4372.97,2816.26 ccw(c4389.19,2832.48) v1@4389.19,2809.54 ; v1@4383.69,2800.04 ccw(c4370.41,2800.04) 4379.8,2809.43 ccw(c4389.19,2818.82) v1@4389.19,2805.54
  Top Layer w8: v2@6695.04,2013.48 cw(c6695.04,1991.75) 6710.4,2007.12 cw(c6725.77,2022.48) v2@6704.04,2022.48 ; v2(6695.04,2022.48) U30.V7@6714.72,2002.8 ; U30.V7@6708.88,2002.8 ccw(c6694.78,2002.8) 6704.75,2012.77 ccw(c6714.72,2022.74) U30.V7@6714.72,2008.64
  MidLayer2 w4: v1@5151.14,2390.09 ccw(c5134.92,2406.31) 5157.86,2406.31 ccw(c5180.79,2406.31) v1@5164.57,2390.09 ; v1@5153.97,2387.26 ccw(c5144.58,2396.65) 5157.86,2396.65 ccw(c5171.14,2396.65) v1@5161.75,2387.26 ; v1(5157.86,2383.37) 5157.86,2418.92 5163.98,2425.04 5374.86,2425.04 5448.52,2351.37 5448.52,2316.71 5465.19,2300.04 5575.15,2300.04 5594.19,2281 5594.19,2215 5584.46,2205.27 5584.46,2046.85 5622.02,2009.29 5622.02,1983.31 5647.34,1958 5695.42,1958 5712.96,1975.54 5734.09,1975.54 5747.09,1962.54 5809.09,1962.54 5828.25,1981.71 6216.25,1981.71 6256.73,2022.19 6544.71,2022.19 v1(6560.52,2006.37)
  Bottom Layer w4: R220.1@3146.18,3030 R216.1@3228.82,3030 3228.82,3046.71 ; R220.1@3149.94,3026.24 cw(c3159.02,3017.16) 3159.02,3030 cw(c3159.02,3042.84) R220.1@3149.94,3033.76 ; R220.1@3152.77,3023.41 cw(c3168.68,3007.5) 3168.68,3030 cw(c3168.68,3052.5) R220.1@3152.77,3036.59 ; R216.1@3222.23,3023.41 ccw(c3206.32,3007.5) 3206.32,3030 ccw(c3206.32,3052.5) R216.1@3222.23,3036.59 ; R216.1@3224.13,3038.54 ccw(c3219.37,3046.71) 3228.82,3046.71 ; R216.1@3225.06,3026.24 ccw(c3215.98,3017.16) 3215.98,3030 ccw(c3215.98,3042.84) R216.1@3225.06,3033.76 ; R216.1@3233.51,3038.54 cw(c3238.27,3046.71) 3228.82,3046.71 ; v1@4326.02,2853.71 ccw(c4303.09,2853.71) 4319.31,2869.93 ccw(c4335.52,2886.14) v1@4335.52,2863.21 ; v1@4330.02,2853.71 ccw(c4316.75,2853.71) 4326.14,2863.1 ccw(c4335.52,2872.49) v1@4335.52,2859.21 ; v1(4335.52,2853.71) 4230.86,2958.37 3645,2958.37 3520,2958.37 3430,3048.37 3230.49,3048.37 3228.82,3046.71 ; v1(4389.19,2800.04) 4570,2800.04 4615.23,2800 4909.01,2506.22 4909.01,2505.97 4925.36,2489.62 4925.36,2475.13 4925,2474.77 4925,2425 4941.63,2408.37 5031.86,2408.37 5040.19,2400.04 5040.19,2366.71 5048.52,2358.37 5132.86,2358.37 v1(5157.86,2383.37) ; v1@4393.08,2796.15 cw(c4402.47,2786.76) 4402.47,2800.04 cw(c4402.47,2813.32) v1@4393.08,2803.93 ; v1@4395.91,2793.32 cw(c4412.13,2777.11) 4412.13,2800.04 cw(c4412.13,2822.98) v1@4395.91,2806.76 ; v1@5148.36,2383.37 cw(c5125.42,2383.37) 5141.64,2367.16 cw(c5157.86,2350.94) v1@5157.86,2373.87 ; v1@5152.36,2383.37 cw(c5139.08,2383.37) 5148.47,2373.99 cw(c5157.86,2364.6) v1@5157.86,2377.87 ; v1@6560.52,1996.87 cw(c6560.52,1973.94) 6576.74,1990.16 cw(c6592.96,2006.37) v1@6570.02,2006.37 ; v1@6560.52,2000.87 cw(c6560.52,1987.6) 6569.91,1996.99 cw(c6579.3,2006.37) v1@6566.02,2006.37 ; v1(6560.52,2006.37) 6603.52,1963.37 6671.52,1963.37 6675.52,1967.37 6675.52,2002.96 v2(6695.04,2022.48) ; v2@6684.04,2022.48 cw(c6657.48,2022.48) 6676.26,2003.7 cw(c6695.04,1984.93) v2@6695.04,2011.48 ; v2@6688.04,2022.48 cw(c6671.14,2022.48) 6683.09,2010.53 cw(c6695.04,1998.58) v2@6695.04,2015.48
PBCTRL.JTAG.HARD.TDO: R217.1 R221.1 U30.T8 | length 4767.8
  Top Layer w8: v2@6773.78,1974.11 cw(c6773.78,1952.38) 6789.14,1967.75 cw(c6804.51,1983.11) v2@6782.78,1983.11 ; v2(6773.78,1983.11) U30.T8@6793.46,1963.43 ; U30.T8@6787.62,1963.43 ccw(c6773.52,1963.43) 6783.49,1973.4 ccw(c6793.46,1983.37) U30.T8@6793.46,1969.27
  MidLayer2 w4: v1(4856.86,2750.04) 4890.19,2783.37 5109.17,2783.37 5112.54,2780 5185.17,2707.37 5228.54,2707.37 5237.88,2716.71 5495.19,2716.71 5570.19,2641.71 5673.52,2641.71 5698.86,2616.37 5698.86,2326.14 5705,2320 5720,2320 5735,2305 5735,2190 5746.63,2178.37 6417.82,2178.37 6496.15,2100.04 6588.86,2100.04 6606.86,2082.04 6751.86,2082.04 6753.52,2080.37 6753.52,2003.37 v2(6773.78,1983.11) ; v1@4856.86,2755.54 ccw(c4856.86,2768.82) 4866.25,2759.43 ccw(c4875.64,2750.04) v1@4862.36,2750.04 ; v1@4856.86,2759.54 ccw(c4856.86,2782.48) 4873.07,2766.26 ccw(c4889.29,2750.04) v1@4866.36,2750.04 ; v2@6762.78,1983.11 ccw(c6736.22,1983.11) 6755,2001.89 ccw(c6773.78,2020.67) v2@6773.78,1994.11 ; v2@6766.78,1983.11 ccw(c6749.88,1983.11) 6761.83,1995.06 ccw(c6773.78,2007.01) v2@6773.78,1990.11
  Bottom Layer w4: R221.1@3146.18,2957.5 R217.1@3228.82,2957.5 3228.82,2973.37 ; R221.1@3149.94,2953.74 cw(c3159.02,2944.66) 3159.02,2957.5 cw(c3159.02,2970.34) R221.1@3149.94,2961.26 ; R221.1@3152.77,2950.91 cw(c3168.68,2935) 3168.68,2957.5 cw(c3168.68,2980) R221.1@3152.77,2964.09 ; R217.1@3222.23,2950.91 ccw(c3206.32,2935) 3206.32,2957.5 ccw(c3206.32,2980) R217.1@3222.23,2964.09 ; R217.1@3224.5,2966.25 ccw(c3220.78,2973.37) 3228.82,2973.37 ; R217.1@3225.06,2953.74 ccw(c3215.98,2944.66) 3215.98,2957.5 ccw(c3215.98,2970.34) R217.1@3225.06,2961.26 ; R217.1@3233.13,2966.25 cw(c3236.86,2973.37) 3228.82,2973.37 ; v1@4850.14,2743.32 ccw(c4833.92,2727.11) 4833.92,2750.04 ccw(c4833.92,2772.98) v1@4850.14,2756.76 ; v1@4852.97,2746.15 ccw(c4843.58,2736.76) 4843.58,2750.04 ccw(c4843.58,2763.32) v1@4852.97,2753.93 ; v1(4856.86,2750.04) 4690.19,2750.04 4648.52,2791.71 4615.19,2825.04 4251.51,2825.04 4126.17,2950.37 3375,2950.37 3350,2975.37 3230.82,2975.37 3228.82,2973.37
PBCTRL.JTAG.HARD.TMS: R218.1 R222.1 U30.U9 | length 8634.2
  Top Layer w4: v1@3189.02,1340 ccw(c3166.09,1340) 3182.31,1356.22 ccw(c3198.52,1372.43) v1@3198.52,1349.5 ; v1@3189.02,2725.04 cw(c3166.09,2725.04) 3182.31,2708.82 cw(c3198.52,2692.61) v1@3198.52,2715.54 ; v1@3193.02,1340 ccw(c3179.75,1340) 3189.14,1349.39 ccw(c3198.52,1358.78) v1@3198.52,1345.5 ; v1@3193.02,2725.04 cw(c3179.75,2725.04) 3189.14,2715.65 cw(c3198.52,2706.26) v1@3198.52,2719.54 ; v1(3198.52,1340) 3181.19,1357.33 3181.19,2707.71 v1(3198.52,2725.04)
  Top Layer w8: v2@6734.41,1934.74 cw(c6734.41,1913.01) 6749.77,1928.38 cw(c6765.14,1943.74) v2@6743.41,1943.74 ; v2(6734.41,1943.74) U30.U9@6754.09,1924.06 ; U30.U9@6748.25,1924.06 ccw(c6734.15,1924.06) 6744.12,1934.03 ccw(c6754.09,1944) U30.U9@6754.09,1929.9
  MidLayer1 w4: v1@3191.81,1273.43 ccw(c3175.59,1289.64) 3198.52,1289.64 ccw(c3221.46,1289.64) v1@3205.24,1273.43 ; v1@3191.81,1333.28 cw(c3175.59,1317.06) 3198.52,1317.06 cw(c3221.46,1317.06) v1@3205.24,1333.28 ; v1@3194.64,1270.6 ccw(c3185.25,1279.99) 3198.52,1279.99 ccw(c3211.8,1279.99) v1@3202.41,1270.6 ; v1@3194.64,1336.11 cw(c3185.25,1326.72) 3198.52,1326.72 cw(c3211.8,1326.72) v1@3202.41,1336.11 ; v1(3198.52,1266.71) v1(3198.52,1340) ; v1@6378.28,1008.28 cw(c6362.06,992.06) 6385,992.06 cw(c6407.93,992.06) v1@6391.72,1008.28 ; v1@6381.11,1011.11 cw(c6371.72,1001.72) 6385,1001.72 cw(c6398.28,1001.72) v1@6388.89,1011.11 ; v1(6385,1015) 6385,985 6435,935 v1(6435,910) ; v1@6428.28,916.72 ccw(c6412.06,932.93) 6435,932.93 ccw(c6457.93,932.93) v1@6441.72,916.72 ; v1@6431.11,913.89 ccw(c6421.72,923.28) 6435,923.28 ccw(c6448.28,923.28) v1@6438.89,913.89 ; v2(6734.41,1943.74) 6754.05,1963.37 6823.52,1963.37 6832.19,1954.71 6832.19,1891.71 6840.52,1883.37 7006.86,1883.37 7023.52,1866.71 7023.52,1469.37 v1(7067.86,1425.04) ; v2@6734.41,1950.74 ccw(c6734.41,1967.64) 6746.36,1955.69 ccw(c6758.31,1943.74) v2@6741.41,1943.74 ; v2@6734.41,1954.74 ccw(c6734.41,1981.3) 6753.19,1962.52 ccw(c6771.96,1943.74) v2@6745.41,1943.74 ; v1@7058.36,1425.04 ccw(c7035.42,1425.04) 7051.64,1441.26 ccw(c7067.86,1457.48) v1@7067.86,1434.54 ; v1@7062.36,1425.04 ccw(c7049.08,1425.04) 7058.47,1434.43 ccw(c7067.86,1443.82) v1@7067.86,1430.54
  MidLayer2 w4: v1@3198.52,1257.21 cw(c3198.52,1234.27) 3214.74,1250.49 cw(c3230.96,1266.71) v1@3208.02,1266.71 ; v1@3198.52,1261.21 cw(c3198.52,1247.93) 3207.91,1257.32 cw(c3217.3,1266.71) v1@3204.02,1266.71 ; v1(3198.52,1266.71) 3232.19,1233.04 4086.96,1233.04 4125.65,1271.73 4234.1,1271.73 4514.64,1552.26 4514.64,1607.57 4540.44,1633.37 4853.88,1633.37 5222.69,1264.56 5222.69,1209.46 5232.94,1199.21 5563.95,1199.21 5594.03,1229.29 5677,1229.29 5714.08,1192.21 5904.63,1192.21 5929.63,1217.21 6029.11,1217.21 6105.36,1140.96 6105.36,1003.91 6184.39,924.88 6385.12,924.88 ; 6385,925 6385.12,924.88 ; v1(6385,1015) 6405,1015 ; v1@6389.26,1011.53 cw(c6396.58,1005.56) 6396.58,1015 cw(c6396.58,1024.44) v1@6389.26,1018.47 ; v1@6392.36,1009 cw(c6405,998.7) 6405,1015 ; v1@6392.36,1021 ccw(c6405,1031.3) 6405,1015 ; v1@6428.28,903.28 ccw(c6412.06,887.06) 6412.06,910 ccw(c6412.06,932.93) v1@6428.28,916.72 ; v1@6431.11,906.11 ccw(c6421.72,896.72) 6421.72,910 ccw(c6421.72,923.28) v1@6431.11,913.89 ; v1(6435,910) 6400,910 6385.12,924.88 ; v1(7067.86,1425.04) 7164.96,1425.04 7174.36,1415.64 7174.36,1120.52 6961.88,908.04 6561.96,908.04 6480,990 6430,990 6405,1015 ; v1@7071.75,1421.15 cw(c7081.14,1411.76) 7081.14,1425.04 cw(c7081.14,1438.32) v1@7071.75,1428.93 ; v1@7074.57,1418.32 cw(c7090.79,1402.11) 7090.79,1425.04 cw(c7090.79,1447.98) v1@7074.57,1431.76
  Bottom Layer w4: R222.1@3146.18,2740 3183.86,2740 v1@3198.52,2725.33 ; R222.1@3149.94,2736.24 cw(c3159.02,2727.16) 3159.02,2740 cw(c3159.02,2752.84) R222.1@3149.94,2743.76 ; R222.1@3152.77,2733.41 cw(c3168.68,2717.5) 3168.68,2740 cw(c3168.68,2762.5) R222.1@3152.77,2746.59 ; v1(3198.52,2725.04) 3213.86,2725.04 R218.1@3228.82,2740 ; R218.1@3219.5,2739.35 cw(c3199.4,2739.01) 3213.62,2724.8 cw(c3226.81,2711.6) R218.1@3228.15,2730.21 ; R218.1@3219.8,2730.99 cw(c3227.64,2723.15) R218.1@3228.44,2734.2 ; R218.1@3220.28,2731.47 ccw(c3212.52,2739.23) R218.1@3223.5,2739.42
PBCTRL.JTAG.SOFT.TCK: R227.1 R231.1 U30.V11 | length 4652.3
  Top Layer w8: v2(6695.04,1825.63) U30.V11@6714.72,1845.31 ; v2@6695.04,1834.63 ccw(c6695.04,1856.36) 6710.4,1840.99 ccw(c6725.77,1825.63) v2@6704.04,1825.63 ; U30.V11@6708.88,1845.31 cw(c6694.78,1845.31) 6704.75,1835.34 cw(c6714.72,1825.37) U30.V11@6714.72,1839.47
  Bottom Layer w4: 3140.19,2557.88 cw(c3182.33,2557.88) R231.1@3152.73,2587.88 ; 3140.19,2567.45 cw(c3172.89,2567.45) R231.1@3149.92,2590.72 ; 3140.19,2577.02 cw(c3163.44,2577.02) R231.1@3147.11,2593.57 ; R231.1@3149.94,2591.24 cw(c3159.02,2582.16) 3159.02,2595 cw(c3159.02,2607.84) R231.1@3149.94,2598.76 ; R231.1@3152.77,2588.41 cw(c3168.68,2572.5) 3168.68,2595 cw(c3168.68,2617.5) R231.1@3152.77,2601.59 ; R227.1@3222.23,2588.41 ccw(c3206.32,2572.5) 3206.32,2595 ccw(c3206.32,2617.5) R227.1@3222.23,2601.59 ; R227.1@3225.06,2591.24 ccw(c3215.98,2582.16) 3215.98,2595 ccw(c3215.98,2607.84) R227.1@3225.06,2598.76 ; R227.1@3228.82,2595 R231.1@3146.18,2595 3140.19,2589.01 3140.19,2558.37 3123.52,2541.71 3123.52,2508.37 3140.19,2491.71 3298.52,2491.71 3316.76,2509.94 3340.06,2509.94 3350,2500 3350,2415 3364.96,2400.04 4337.82,2400.04 4348.54,2389.32 4401.4,2336.45 4414.52,2323.34 4414.52,2036.48 4426,2025 4715,2025 5102.23,2025.04 5110.56,2016.71 5260.19,2016.71 5419.19,1857.71 5886.49,1857.71 5919.2,1825 6084.88,1825 6110.17,1799.71 6248.19,1799.71 6273.52,1825.04 6290.19,1841.71 6584.86,1841.71 6590.19,1847.04 6665.19,1847.04 6687.19,1825.04 6698.52,1825.04 6698.52,1825.63 v2(6695.04,1825.63) ; 6669.41,1842.82 ccw(c6686.73,1860.14) v2@6692.47,1836.32 ; 6674.46,1837.77 ccw(c6688.69,1852.01) v2@6693.4,1832.44 ; 6679.51,1832.73 ccw(c6690.65,1843.87) v2@6694.34,1828.55 ; 6682.23,1830 cw(c6677.85,1825.63) v2@6684.04,1825.63
PBCTRL.JTAG.SOFT.TDI: R224.1 R228.1 U30.R12 | length 5600.7
  Top Layer w8: v2(6813.15,1786.26) U30.R12@6832.83,1805.94 ; v2@6813.15,1795.26 ccw(c6813.15,1816.99) 6828.51,1801.62 ccw(c6843.88,1786.26) v2@6822.15,1786.26 ; U30.R12@6826.99,1805.94 cw(c6812.89,1805.94) 6822.86,1795.97 cw(c6832.83,1786) U30.R12@6832.83,1800.1
  MidLayer1 w4: v1(2970,2408.37) 3106.86,2408.37 3165.19,2466.71 3165.19,2788.37 v1(3193.52,2816.71) ; v1@2973.89,2404.49 cw(c2983.28,2395.1) 2983.28,2408.37 cw(c2983.28,2421.65) v1@2973.89,2412.26 ; v1@2976.72,2401.66 cw(c2992.93,2385.44) 2992.93,2408.37 cw(c2992.93,2431.31) v1@2976.72,2415.09 ; v1@3184.02,2816.71 cw(c3161.09,2816.71) 3177.31,2800.49 cw(c3193.52,2784.27) v1@3193.52,2807.21 ; v1@3188.02,2816.71 cw(c3174.75,2816.71) 3184.13,2807.32 cw(c3193.52,2797.93) v1@3193.52,2811.21
  MidLayer2 w4: v1@5049.52,1973.87 cw(c5049.52,1950.94) 5065.74,1967.16 cw(c5081.96,1983.37) v1@5059.02,1983.37 ; v1@5049.52,1977.87 cw(c5049.52,1964.6) 5058.91,1973.99 cw(c5068.3,1983.37) v1@5055.02,1983.37 ; v1(5049.52,1983.37) 5192.19,1840.71 5222.52,1840.71 5231.69,1849.87 5700.66,1849.87 5719.82,1830.71 5892.19,1830.71 5906.19,1816.71 6277.86,1816.71 6319.52,1858.37 6431.86,1858.37 6444.19,1846.04 6781.19,1846.04 6793.86,1833.37 6793.86,1805.55 6798.52,1800.89 v2(6813.15,1786.26)
  Bottom Layer w4: v1@2970,2398.87 cw(c2970,2375.94) 2986.22,2392.16 cw(c3002.43,2408.37) v1@2979.5,2408.37 ; v1@2970,2402.87 cw(c2970,2389.6) 2979.39,2398.99 cw(c2988.78,2408.37) v1@2975.5,2408.37 ; v1(2970,2408.37) 3054.87,2323.5 3282.02,2323.5 3311.02,2294.5 3375.5,2294.5 3379,2291 3666.15,2291 3666.28,2290.87 4357.69,2290.87 4381.52,2267.04 4381.52,2005 4397.71,1988.81 4946.07,1988.81 4951.5,1983.37 v1(5049.52,1983.37) ; R228.1@3146.18,2812.5 3189.52,2812.5 3193.52,2816.5 v1(3193.52,2816.71) 3224.61,2816.71 R224.1@3228.82,2812.5 ; R228.1@3149.94,2808.74 cw(c3159.02,2799.66) 3159.02,2812.5 cw(c3159.02,2825.34) R228.1@3149.94,2816.26 ; R228.1@3152.77,2805.91 cw(c3168.68,2790) 3168.68,2812.5 cw(c3168.68,2835) R228.1@3152.77,2819.09 ; 3160.43,2812.5 ccw(c3160.43,2849.8) v1@3186.81,2823.43 ; 3170.09,2812.5 ccw(c3170.09,2840.14) v1@3189.64,2820.6 ; 3179.74,2812.5 ccw(c3179.74,2830.49) v1@3192.46,2817.77 ; 3180.75,2812.5 cw(c3180.75,2803.93) v1@3186.81,2809.99 ; v1@3197.35,2816.71 cw(c3197.35,2781.52) R224.1@3222.23,2806.4 ; v1@3197.41,2812.82 cw(c3206.8,2803.43) 3206.8,2816.71 cw(c3206.8,2829.99) v1@3197.41,2820.6 ; v1@3200.24,2809.99 cw(c3216.46,2793.77) 3216.46,2816.71 cw(c3216.46,2839.64) v1@3200.24,2823.43 ; 3207.01,2816.71 cw(c3207.01,2791.18) R224.1@3225.06,2809.23 ; 3215.29,2816.71 ccw(c3215.29,2826.52) R224.1@3222.23,2819.58 ; 3216.66,2816.71 cw(c3216.66,2800.84) R224.1@3227.89,2812.06 ; v1@5042.81,1976.66 ccw(c5026.59,1960.44) 5026.59,1983.37 ccw(c5026.59,2006.31) v1@5042.81,1990.09 ; v1@5045.64,1979.49 ccw(c5036.25,1970.1) 5036.25,1983.37 ccw(c5036.25,1996.65) v1@5045.64,1987.26
PBCTRL.JTAG.SOFT.TDO: R225.1 R229.1 U30.Y11 | length 5054.2
  Top Layer w4: v1@3222.36,2635.04 cw(c3199.42,2635.04) 3215.64,2618.82 cw(c3231.86,2602.61) v1@3231.86,2625.54 ; v1@3226.36,2635.04 cw(c3213.08,2635.04) 3222.47,2625.65 cw(c3231.86,2616.26) v1@3231.86,2629.54 ; v1(3231.86,2635.04) 3197.19,2600.37 3197.19,2435.98 3264.86,2368.31 3264.86,2260.14 3280,2245 v1(3355,2245) ; v1@3348.28,2238.28 ccw(c3332.06,2222.06) 3332.06,2245 ccw(c3332.06,2267.93) v1@3348.28,2251.72 ; v1@3351.11,2241.11 ccw(c3341.72,2231.72) 3341.72,2245 ccw(c3341.72,2258.28) v1@3351.11,2248.89 ; v1@6041.81,1805.76 ccw(c6025.59,1821.98) 6048.52,1821.98 ccw(c6071.46,1821.98) v1@6055.24,1805.76 ; v1@6041.81,1839.99 cw(c6025.59,1823.77) 6048.52,1823.77 cw(c6071.46,1823.77) v1@6055.24,1839.99 ; v1@6044.64,1802.93 ccw(c6035.25,1812.32) 6048.52,1812.32 ccw(c6061.8,1812.32) v1@6052.41,1802.93 ; v1@6044.64,1842.82 cw(c6035.25,1833.43) 6048.52,1833.43 cw(c6061.8,1833.43) v1@6052.41,1842.82 ; v1(6048.52,1799.04) v1(6048.52,1846.71)
  Top Layer w8: v2(6616.3,1825.63) U30.Y11@6635.98,1845.31 ; v2@6616.3,1834.63 ccw(c6616.3,1856.36) 6631.66,1840.99 ccw(c6647.03,1825.63) v2@6625.3,1825.63 ; U30.Y11@6630.14,1845.31 cw(c6616.04,1845.31) 6626.01,1835.34 cw(c6635.98,1825.37) U30.Y11@6635.98,1839.47
  MidLayer2 w4: v1@3355,2235.5 cw(c3355,2180.13) 3394.15,2219.28 ; v1@3355,2239.5 cw(c3355,2193.79) 3387.32,2226.11 ; v1@3355,2243.5 cw(c3355,2207.44) 3380.5,2232.94 ; v1(3355,2245) 3368.43,2245 3433.43,2180 4687.77,2180 4700.77,2167 4972.62,2167 5273.75,1865.87 5707.28,1865.87 5726.45,1846.71 v1(6048.52,1846.71) ; v1@3355,2247.5 cw(c3355,2221.1) 3373.67,2239.77 ; v1@3355,2251.5 cw(c3355,2234.76) 3366.84,2246.6 ; v1@6041.81,1839.99 ccw(c6025.59,1823.77) 6025.59,1846.71 ccw(c6025.59,1869.64) v1@6041.81,1853.43 ; v1@6044.64,1842.82 ccw(c6035.25,1833.43) 6035.25,1846.71 ccw(c6035.25,1859.99) v1@6044.64,1850.6 ; v1@6046.76,1800.81 cw(c6065.02,1782.54) 6065.02,1808.37 ; v1(6048.52,1799.04) 6057.86,1808.37 6281.86,1808.37 6323.52,1850.04 6428.88,1850.04 6453.29,1825.63 v2(6616.3,1825.63) ; v1@6049.58,1797.98 cw(c6074.68,1772.89) 6074.68,1808.37 ; v1@6052.41,1795.15 cw(c6084.34,1763.23) 6084.34,1808.37 ; v1@6055.24,1792.32 cw(c6093.99,1753.57) 6093.99,1808.37 ; v2@6608.52,1817.85 ccw(c6589.74,1799.07) 6589.74,1825.63 ccw(c6589.74,1852.19) v2@6608.52,1833.41 ; v2@6611.35,1820.68 ccw(c6599.4,1808.73) 6599.4,1825.63 ccw(c6599.4,1842.53) v2@6611.35,1830.58
  Bottom Layer w4: R229.1@3146.18,2667.5 R225.1@3228.82,2667.5 3228.82,2646.41 ; R229.1@3149.94,2663.74 cw(c3159.02,2654.66) 3159.02,2667.5 cw(c3159.02,2680.34) R229.1@3149.94,2671.26 ; R229.1@3152.77,2660.91 cw(c3168.68,2645) 3168.68,2667.5 cw(c3168.68,2690) R229.1@3152.77,2674.09 ; R225.1@3222.23,2660.91 ccw(c3206.32,2645) 3206.32,2667.5 ccw(c3206.32,2690) R225.1@3222.23,2674.09 ; R225.1@3222.67,2660.01 cw(c3210.72,2646.41) 3228.82,2646.41 ; R225.1@3225.06,2663.74 ccw(c3215.98,2654.66) 3215.98,2667.5 ccw(c3215.98,2680.34) R225.1@3225.06,2671.26 ; v1@3225.14,2641.76 ccw(c3216.26,2650.64) 3228.82,2650.64 ; R225.1@3225.31,2663.01 cw(c3218.49,2655.25) 3228.82,2655.25 cw(c3239.15,2655.25) R225.1@3232.33,2663.01 ; 3228.82,2655.65 ccw(c3252.47,2655.65) v1@3235.75,2638.93 ; R225.1@3228.82,2665.31 ccw(c3262.13,2665.31) v1@3238.57,2641.76 ; v1(3231.86,2635.04) 3231.86,2643.37 3228.82,2646.41 ; R225.1@3234.97,2660.01 ccw(c3246.92,2646.41) 3228.82,2646.41
PBCTRL.JTAG.SOFT.TMS: R226.1 R230.1 U30.W13 | length 4544.3
  Top Layer w8: v2(6655.67,1746.89) U30.W13@6675.35,1766.57 ; v2@6655.67,1755.89 ccw(c6655.67,1777.62) 6671.03,1762.25 ccw(c6686.4,1746.89) v2@6664.67,1746.89 ; U30.W13@6669.51,1766.57 cw(c6655.41,1766.57) 6665.38,1756.6 cw(c6675.35,1746.63) U30.W13@6675.35,1760.73
  MidLayer1 w4: v1@6481.86,1871.87 cw(c6481.86,1864.23) 6487.26,1869.64 ; v1(6481.86,1881.37) 6481.86,1875.04 6498.52,1858.37 6658.19,1858.37 6674.86,1841.71 6674.86,1769.04 ; v1@6487.13,1879.83 ccw(c6500.26,1875.98) 6490.59,1866.31 ; v1@6490.97,1878.7 ccw(c6507.63,1873.82) 6495.36,1861.54 ; v2(6655.67,1746.89) 6655.67,1750.04 6655.86,1750.04 6674.86,1769.04 ; v2@6655.67,1757.89 ccw(c6655.67,1777.29) 6669.39,1763.57 ; v2@6662.66,1747.29 cw(c6682.83,1748.44) 6668.54,1762.73 ; v2@6666.65,1747.52 cw(c6694.77,1749.12) 6674.86,1769.04
  Bottom Layer w4: R230.1@3142.6,2513.4 cw(c3140.37,2508.04) 3146.18,2508.04 ; R230.1@3146.18,2522.5 3146.18,2508.04 ; R230.1@3149.76,2513.4 ccw(c3151.99,2508.04) 3146.18,2508.04 ; R226.1@3267.8,2513.32 cw(c3265.87,2508.38) 3271.18,2508.38 ; R226.1@3274.56,2513.32 ccw(c3276.49,2508.38) 3271.18,2508.38 ; R226.1@3274.94,2519.23 cw(c3288.97,2505.21) 3288.97,2525.04 ; R226.1@3277.77,2516.4 cw(c3298.62,2495.55) 3298.62,2525.04 ; R226.1@3277.77,2529.58 ccw(c3288.73,2540.54) 3288.73,2525.04 ; v1@6472.36,1881.37 ccw(c6449.42,1881.37) 6465.64,1897.59 ccw(c6481.86,1913.81) v1@6481.86,1890.87 ; v1@6476.36,1881.37 ccw(c6463.08,1881.37) 6472.47,1890.76 ccw(c6481.86,1900.15) v1@6481.86,1886.87 ; v1(6481.86,1881.37) 6429.86,1933.37 5873.52,1933.37 5805.86,1865.71 5422.5,1865.71 5263.17,2025.04 5113.54,2025.04 5105.21,2033.37 4428.94,2033.37 4422.52,2039.79 4422.52,2326.65 4341.13,2408.04 3626.96,2408.04 3368.27,2408.04 3358,2418.31 3358,2507.04 3340,2525.04 3273.72,2525.04 R226.1@3271.18,2522.5 3271.18,2508.37 ; 3146.18,2508.04 3154.18,2500.04 3262.85,2500.04 3271.18,2508.37
PBCTRL.SPARE1: EXTHDR1.39 U30.V9 | length 6645.7
  Top Layer w4: v1@1526.18,2978.82 ccw(c1509.96,2995.04) 1532.9,2995.04 ccw(c1555.83,2995.04) v1@1539.61,2978.82 ; EXTHDR1.39@1527.24,3021.07 cw(c1513.58,3007.42) 1532.9,3007.42 cw(c1552.21,3007.42) EXTHDR1.39@1538.55,3021.07 ; v1@1529.01,2975.99 ccw(c1519.62,2985.38) 1532.9,2985.38 ccw(c1546.18,2985.38) v1@1536.79,2975.99 ; v1(1532.9,2972.1) EXTHDR1.39@1532.9,3071.85
  Top Layer w8: v2@6695.04,1934.74 cw(c6695.04,1913.01) 6710.4,1928.38 cw(c6725.77,1943.74) v2@6704.04,1943.74 ; v2(6695.04,1943.74) U30.V9@6714.72,1924.06 ; U30.V9@6708.88,1924.06 ccw(c6694.78,1924.06) 6704.75,1934.03 ccw(c6714.72,1944) U30.V9@6714.72,1929.9
  MidLayer1 w4: v1@1526.9,2964.74 cw(c1516.6,2952.1) 1532.9,2952.1 ; v1@1529.42,2967.84 cw(c1523.46,2960.52) 1532.9,2960.52 cw(c1542.33,2960.52) v1@1536.37,2967.84 ; v1(1532.9,2972.1) 1532.9,2952.1 ; v1@1538.9,2964.74 ccw(c1549.2,2952.1) 1532.9,2952.1 ; v1@1938.28,2261.72 ccw(c1915.97,2284.03) 1947.52,2284.03 ; v1@1941.11,2258.89 ccw(c1925.63,2274.37) 1947.52,2274.37 ; v1(1945,2255) 1945.37,2255 1947.52,2257.15 1947.52,2564.73 1603.54,2908.71 1576.29,2908.71 1532.9,2952.1 ; 1947.52,2271.84 ccw(c1961.84,2271.84) v1@1951.72,2261.72
  MidLayer2 w4: v1@1945,2245.5 cw(c1945,2222.56) 1961.22,2238.78 cw(c1977.43,2255) v1@1954.5,2255 ; v1@1945,2249.5 cw(c1945,2236.22) 1954.39,2245.61 cw(c1963.78,2255) v1@1950.5,2255 ; v1(1945,2255) 1970,2230 2045.44,2230 2083.44,2268 2213.31,2268 2222.81,2258.5 2257.19,2258.5 2269.19,2270.5 3365.56,2270.5 3380.5,2255.56 3436.06,2200 4690.39,2200 4706.69,2183.71 4978.54,2183.71 5012.21,2150.04 5106.86,2150.04 5248.52,2008.37 5248.52,1916.04 5290.7,1873.87 5710.6,1873.87 5729.76,1854.71 5976.33,1854.71 6055.33,1933.71 6295.92,1933.71 6329.58,1900.04 6512.21,1900.04 6550.21,1862.04 6727.19,1862.04 6753.52,1888.37 6753.52,1922.37 6751.86,1924.04 6714.74,1924.04 v2(6695.04,1943.74) ; v2@6695.04,1932.74 cw(c6695.04,1906.18) 6713.82,1924.96 cw(c6732.6,1943.74) v2@6706.04,1943.74 ; v2@6695.04,1936.74 cw(c6695.04,1919.84) 6706.99,1931.79 cw(c6718.94,1943.74) v2@6702.04,1943.74
PBCTRL.SPARE2: EXTHDR1.41 U30.T10 | length 6692.7
  Top Layer w4: EXTHDR1.41@1495.75,3122.63 ccw(c1482.16,3136.25) 1501.4,3136.25 ; EXTHDR1.41@1501.4,3071.85 1501.4,3136.25 ; EXTHDR1.41@1507.05,3122.63 cw(c1520.64,3136.25) 1501.4,3136.25 ; v1(1515.19,3150.04) 1501.4,3136.25
  Top Layer w8: v2@6773.78,1895.37 cw(c6773.78,1873.64) 6789.14,1889.01 cw(c6804.51,1904.37) v2@6782.78,1904.37 ; v2(6773.78,1904.37) U30.T10@6793.46,1884.68 ; U30.T10@6787.62,1884.68 ccw(c6773.52,1884.68) 6783.49,1894.66 ccw(c6793.46,1904.63) U30.T10@6793.46,1890.53
  MidLayer1 w4: v1(1515.19,3150.04) 1614.58,3150.04 1727,3037.62 1727,2824.55 2090.19,2461.36 v1(2090.19,2250) ; v1@1519.08,3146.15 cw(c1528.47,3136.76) 1528.47,3150.04 cw(c1528.47,3163.32) v1@1519.08,3153.93 ; v1@1521.91,3143.32 cw(c1538.13,3127.11) 1538.13,3150.04 cw(c1538.13,3172.98) v1@1521.91,3156.76 ; v1@2083.47,2256.72 ccw(c2067.26,2272.93) 2090.19,2272.93 ccw(c2113.13,2272.93) v1@2096.91,2256.72 ; v1@2086.3,2253.89 ccw(c2076.91,2263.28) 2090.19,2263.28 ccw(c2103.47,2263.28) v1@2094.08,2253.89
  MidLayer2 w4: v1(2090.19,2250) 2100.19,2260 2210,2260 2219.5,2250.5 2260.5,2250.5 2272.5,2262.5 3362.25,2262.5 3372.5,2252.25 3434.75,2190 4689.08,2190 4704.08,2175 4975.94,2175 5014.94,2136 5070.9,2136 5125.52,2081.37 v1(5125.52,2055.37) ; v1@5118.81,2062.09 ccw(c5102.59,2078.31) 5125.52,2078.31 ccw(c5148.46,2078.31) v1@5132.24,2062.09 ; v1@5121.64,2059.26 ccw(c5112.25,2068.65) 5125.52,2068.65 ccw(c5138.8,2068.65) v1@5129.41,2059.26
  Bottom Layer w4: v1(5125.52,2055.37) 5155.37,2055.37 ; v1@5129.41,2051.49 cw(c5138.8,2042.1) 5138.8,2055.37 cw(c5138.8,2068.65) v1@5129.41,2059.26 ; v1@5132.24,2048.66 cw(c5148.46,2032.44) 5148.46,2055.37 cw(c5148.46,2078.31) v1@5132.24,2062.09 ; 5155,2055 5155.37,2055.37 ; v2@6762.78,1904.37 cw(c6736.22,1904.37) 6755,1885.59 cw(c6773.78,1866.82) v2@6773.78,1893.37 ; v2@6766.78,1904.37 cw(c6749.88,1904.37) 6761.83,1892.42 cw(c6773.78,1880.47) v2@6773.78,1897.37 ; v2(6773.78,1904.37) 6752.79,1883.37 6605.52,1883.37 6590.19,1898.71 6590.19,1909.71 6583.19,1916.71 6499.52,1916.71 6474.52,1941.71 5826.82,1941.71 5793.82,1908.71 5759.5,1908.71 5742.38,1891.59 5720,1891.59 5718.91,1892.68 5678.21,1933.37 5573.86,1933.37 5565.19,1942.04 5565.19,2055.39 5553.54,2067.04 5167.04,2067.04 5155.37,2055.37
